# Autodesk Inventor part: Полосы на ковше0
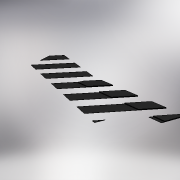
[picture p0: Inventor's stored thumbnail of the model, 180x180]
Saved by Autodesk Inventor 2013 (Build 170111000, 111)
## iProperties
Created: 2012-02
Part Number: Полосы на ковше0
Material: Aluminum-6061
Document SubType Name: Modeling
Designer: tedescj
Density: 2.71 g/cm^3
Mass: 1247.09 g
Surface Area: 3414.78 cm^2
Volume: 460.181 cm^3
Author: tedescj
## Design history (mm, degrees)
sketch "Sketch1"
  geometry: L1 (105.184, -95.669)-(560.563, -166.165); L2 (26.04, -191.675)-(45.636, -388); L3 (26.04, -191.675)-(105.184, -95.669) reference; L4 (185.636, -108.123)-(35.838, -289.838); L5 (266.087, -120.578)-(45.636, -388); L6 (45.636, -388)-(495.113, -388); L7 (346.539, -133.032)-(126.088, -400.455); L8 (426.99, -145.487)-(206.539, -412.909); L9 (507.442, -157.942)-(286.991, -425.364); L10 (367.443, -437.818)-(594.631, -162.223); L11 (447.894, -450.273)-(694.915, -150.62); L12 (528.346, -462.727)-(795.198, -139.017); L13 (608.797, -475.182)-(895.482, -127.414); L14 (689.249, -487.636)-(995.766, -115.81); L15 (769.7, -500.091)-(1096.049, -104.207); L16 (870.71, -515.728)-(899.043, -453.237) reference; L17 (1014.346, -537.964)-(960.99, -655.645) reference; L18 (1149.652, -239.537)-(1217.375, -90.169); L19 (1066.993, -249.502)-(1149.652, -239.537) reference; L20 (850.152, -512.546)-(899.043, -453.237); L21 (1066.993, -249.502)-(1196.333, -92.604); L22 (850.152, -512.546)-(870.71, -515.728); 1 further point; 1 other entity
  constraints: 44 end point, 13 parallel, 6 point on line, 1 collinear, 1 horizontal, 1 midpoint, 33 other
  dimensions: "d1" = 70 distance between parallel lines of L4 L3; "d2" = 70 distance between parallel lines of L5 L4 (= d1); "d3" = 1.53589 dimension on L6; "d4" = 388 vertical distance of L2.end point (0, 0); "d5" = 104.5 deg dimension on L2; "d6" = 298 dimension on L1; "d7" = 28.72812 dimension on L1; "d8" = 70 distance between parallel lines of L7 L5 (= d1); "d9" = 70 distance between parallel lines of L8 L7 (= d2); "d10" = 70 distance between parallel lines of L9 L8 (= d1); "d11" = 70 distance between parallel lines of L10 L9 (= d2); "d12" = 70 distance between parallel lines of L11 L10 (= d1); "d13" = 70 distance between parallel lines of L12 L11 (= d2); "d14" = 70 distance between parallel lines of L13 L12 (= d1); "d15" = 70 distance between parallel lines of L14 L13 (= d2); "d16" = 70 distance between parallel lines of L15 L14 (= d1)
feature "Surface1"
feature "Surface2"
feature "Trim1"
feature "Stitch Surface1"
feature "OffsetSrf1" dims "d18" = 1, "d19" = 1
feature "OffsetSrf2" dims "d20" = 1 (= d18), "d21" = 1
feature "OffsetSrf3" dims "d22" = 1 (= d18), "d23" = 1
feature "OffsetSrf4" dims "d24" = 1 (= d18), "d25" = 1
feature "Trim2"
feature "Trim10"
feature "Extend7" dims "d32" = 5
feature "Extend8" dims "d33" = 7.25
feature "Trim11"
feature "Trim12"
feature "Extend9" dims "d34" = 5
feature "Extend10" dims "d35" = 5
feature "Extend11" dims "d36" = 5
feature "Extend12" dims "d37" = 5
feature "Trim13"
feature "Trim14"
feature "Trim15"
feature "Trim16"
feature "Stitch Surface2"
feature "Trim17"
feature "Stitch Surface3"
extrude "Extrusion1" new body sketch "Sketch1" stored distance "d38" = 10; taper "d39" = 0 deg
split "Split1"
body "Solid1"
body "Srf3"
body "Srf4"
body "Srf5"
body "Srf6"
body "Srf7"
body "Srf8"
body "Srf9"
body "Srf1"
body "Srf2"
